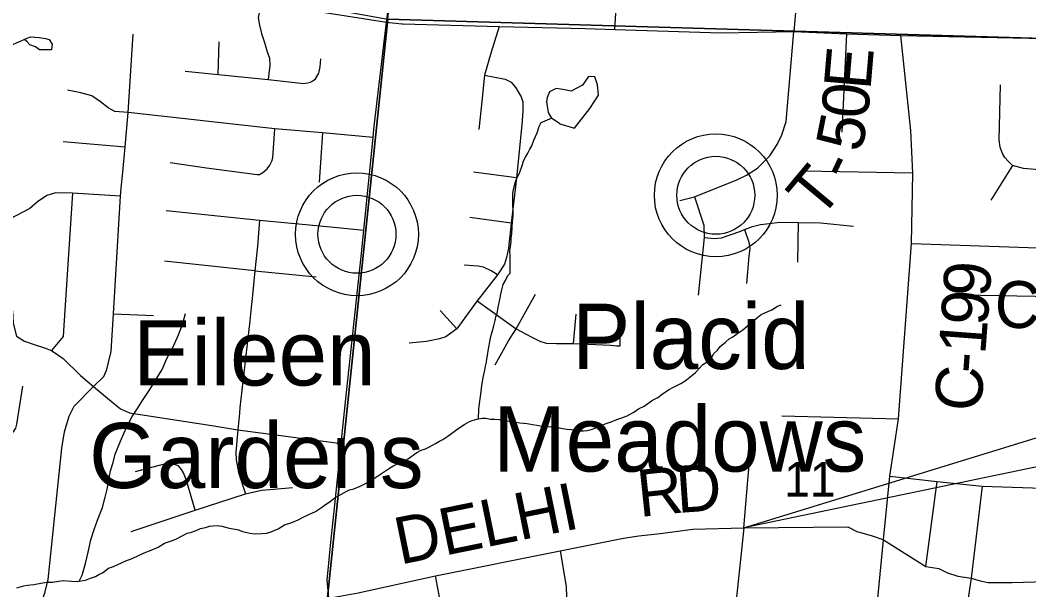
# Model space of a CAD drawing. Extents: x 0 to 34, y -2 to 22.
# Drawn here: x 4.698 to 5.919, y 16.041 to 16.731 of the extents above; entities that cross this region are included whole.
import ezdxf

# ---------------------------------------------------------------- set-up
doc = ezdxf.new("R2010")
doc.units = 0
for name, color, linetype in [('GM_X_County_Road', 7, 'Continuous'), ('GM_X_County_Road_Text', 7, 'Continuous'), ('GM_X_Minor_Lake', 7, 'Continuous'), ('GM_X_Minor_River', 7, 'Continuous'), ('GM_X_Section', 7, 'Continuous'), ('GM_X_Section_Text', 7, 'Continuous'), ('GM_X_Township_Road', 7, 'Continuous'), ('GM_X_Township_Road_Text', 7, 'Continuous'), ('GM_X_Unincorporated', 7, 'Continuous'), ('GM_X_Unincorporated_Location', 7, 'Continuous'), ('GM_X_Unincorporated_Text', 7, 'Continuous'), ('SH_Data', 7, 'Continuous'), ('SH_Text', 7, 'Continuous')]:
    doc.layers.add(name, color=color, linetype=linetype)

msp = doc.modelspace()

# ---------------------------------------------------------------- linework, layer by layer
at = {"layer": 'GM_X_County_Road'}
msp.add_line((5.6417, 16.798), (5.6344, 16.7168), dxfattribs=at)
for points in [[(5.075, 16.1095), (5.0801, 16.1592), (5.0864, 16.2182), (5.0917, 16.2685), (5.1105, 16.4445), (5.1137, 16.4765), (5.125, 16.5888), (5.1259, 16.5986), (5.1413, 16.7282), (5.1541, 16.8214), (5.1564, 16.873), (5.1627, 16.9374), (5.1803, 17.1286), (5.1858, 17.1668)], [(4.9892, 16.752), (5.1413, 16.7282), (5.1599, 16.7264), (5.1609, 16.7264)], [(5.1609, 16.7264), (5.2776, 16.7232), (5.3822, 16.7204), (5.4178, 16.7193), (5.5463, 16.7152), (5.6344, 16.7168)], [(5.6344, 16.7168), (5.6981, 16.7142), (5.7642, 16.7123)], [(5.7432, 16.1015), (5.7506, 16.1784), (5.7611, 16.248), (5.7771, 16.4603), (5.7787, 16.5454), (5.7761, 16.597), (5.7642, 16.7123)], [(5.7642, 16.7123), (5.9195, 16.7087), (5.9635, 16.7073), (5.991, 16.7068), (6.1316, 16.7045)], [(5.7771, 16.4603), (5.9772, 16.4534), (6.1008, 16.4492), (6.222, 16.4333), (6.2538, 16.4291)], [(5.7506, 16.1784), (5.8081, 16.1722), (5.8625, 16.1664), (5.9478, 16.1635), (6.0702, 16.1495), (6.1855, 16.1382), (6.345, 16.1172), (6.3726, 16.1142), (6.4077, 16.1125), (6.4437, 16.112), (6.4766, 16.1114), (6.5789, 16.1097)], [(5.0285, 16.0123), (5.0457, 16.0195), (5.0715, 16.0307), (5.1068, 16.0374), (5.2004, 16.0579), (5.3517, 16.0882), (5.4284, 16.1035), (5.4467, 16.1064), (5.4725, 16.1091), (5.512, 16.1143), (5.5739, 16.1159), (5.6997, 16.1172), (5.7116, 16.111), (5.7142, 16.1106), (5.7294, 16.1063), (5.734, 16.1047)], [(5.07, 16.0607), (5.0743, 16.1026), (5.075, 16.1095)], [(5.7054, 15.7447), (5.7226, 15.8889), (5.7432, 16.1015)], [(5.734, 16.1047), (5.7432, 16.1015), (5.7945, 16.0693), (5.8101, 16.0667), (5.8206, 16.0614), (5.8332, 16.0573), (5.8492, 16.0548), (5.8602, 16.0518), (5.8698, 16.0499), (5.8987, 16.0499), (5.9535, 16.0513)], [(5.0715, 16.0307), (5.0692, 16.0529), (5.07, 16.0607)], [(5.2096, 16.0107), (5.2004, 16.0579)]]:
    msp.add_lwpolyline(points, dxfattribs=at)
at = {"layer": 'GM_X_Minor_Lake'}
for points in [[(4.6858, 16.6999), (4.7062, 16.7089), (4.71, 16.7107), (4.7206, 16.7096), (4.7282, 16.7083), (4.7327, 16.7074), (4.7364, 16.7016), (4.7354, 16.6948), (4.732, 16.6949), (4.721, 16.6948), (4.7162, 16.6984), (4.7094, 16.7008), (4.7057, 16.7047)], [(4.7057, 16.7047), (4.7028, 16.7074)], [(5.3512, 16.6052), (5.3687, 16.6), (5.3874, 16.6238), (5.3981, 16.6399), (5.3969, 16.6525), (5.3933, 16.662), (5.3857, 16.6626), (5.3786, 16.6518), (5.3702, 16.6474), (5.3648, 16.6449), (5.3546, 16.6467), (5.3467, 16.648), (5.3386, 16.644), (5.3358, 16.6369)], [(5.3358, 16.637), (5.3349, 16.6319), (5.3369, 16.619), (5.3412, 16.612)], [(5.3512, 16.6052), (5.3412, 16.612)]]:
    msp.add_lwpolyline(points, dxfattribs=at)
at = {"layer": 'GM_X_Minor_River'}
for points in [[(5.2911, 16.4242), (5.2909, 16.4451), (5.2907, 16.4512), (5.2912, 16.4565), (5.2921, 16.4622), (5.2923, 16.4671), (5.2928, 16.4717), (5.2934, 16.4797), (5.2939, 16.4869), (5.2945, 16.4933), (5.2947, 16.4998), (5.2941, 16.5082), (5.294, 16.5158), (5.2941, 16.5211), (5.295, 16.5253), (5.2963, 16.5306), (5.2975, 16.5348), (5.2992, 16.5393), (5.3024, 16.5453), (5.3057, 16.5559), (5.307, 16.5604), (5.3097, 16.5649), (5.3125, 16.5698), (5.3149, 16.5743), (5.3173, 16.5784), (5.3198, 16.5852), (5.3235, 16.5942), (5.326, 16.6018), (5.3284, 16.6066), (5.3412, 16.6121)], [(5.2526, 16.2481), (5.2532, 16.2602), (5.2557, 16.2811), (5.2566, 16.2883), (5.2575, 16.2929), (5.2584, 16.2978), (5.2602, 16.3069), (5.2611, 16.3118), (5.2623, 16.3164), (5.2628, 16.3205), (5.2637, 16.3247), (5.2647, 16.3327), (5.2655, 16.3368), (5.2664, 16.3414), (5.2677, 16.3478), (5.2699, 16.3561), (5.2711, 16.3607), (5.2728, 16.3671), (5.2737, 16.3713), (5.2753, 16.3758), (5.2763, 16.3826), (5.2776, 16.3883), (5.2784, 16.3925), (5.2798, 16.3989), (5.281, 16.4042), (5.2824, 16.4106), (5.2852, 16.4155), (5.288, 16.4215), (5.2911, 16.4242)], [(5.3545, 16.2361), (5.3594, 16.2356), (5.3651, 16.235), (5.37, 16.2345), (5.3753, 16.2336), (5.3799, 16.2335), (5.384, 16.2337), (5.389, 16.2351), (5.3948, 16.2372), (5.399, 16.239), (5.4071, 16.2422), (5.4132, 16.2443), (5.4202, 16.2472), (5.4251, 16.2486), (5.4328, 16.2514), (5.4406, 16.2562), (5.4464, 16.2602), (5.4533, 16.2634), (5.4634, 16.2704), (5.4696, 16.2736), (5.475, 16.2777), (5.4827, 16.2832), (5.4889, 16.2864), (5.4978, 16.2907), (5.5028, 16.294), (5.511, 16.3003), (5.5153, 16.304), (5.5196, 16.3084), (5.5243, 16.3136), (5.5297, 16.3169), (5.5352, 16.3228), (5.5376, 16.327), (5.5422, 16.331), (5.5454, 16.3355), (5.5516, 16.3407), (5.5563, 16.3447), (5.5605, 16.3473), (5.5667, 16.3517), (5.5726, 16.3557), (5.5807, 16.3627), (5.5858, 16.3667), (5.5909, 16.3712), (5.5951, 16.3741), (5.6028, 16.3781), (5.6078, 16.3798), (5.6148, 16.3842), (5.6193, 16.386)], [(4.7688, 16.0513), (4.7725, 16.0586), (4.7766, 16.0726), (4.7799, 16.0865), (4.7833, 16.1013), (4.787, 16.1138), (4.791, 16.1254), (4.7971, 16.1405), (4.8004, 16.153), (4.8029, 16.1628), (4.8071, 16.1848), (4.81, 16.1949), (4.8125, 16.2052), (4.819, 16.221), (4.8261, 16.2368), (4.8333, 16.2507), (4.8396, 16.2604), (4.8455, 16.2702), (4.8545, 16.2833), (4.8631, 16.2972), (4.8694, 16.3077), (4.875, 16.3208), (4.8829, 16.3351), (4.8893, 16.3498), (4.8942, 16.3622), (4.8979, 16.3754)], [(4.6936, 16.0432), (4.702, 16.0456), (4.7066, 16.0466), (4.7139, 16.0475), (4.7227, 16.0488), (4.7299, 16.0501), (4.7368, 16.0503), (4.7498, 16.0523), (4.7596, 16.0512), (4.7665, 16.051), (4.7714, 16.0517), (4.7768, 16.0526), (4.7829, 16.0548), (4.7887, 16.0569), (4.7929, 16.0594), (4.7972, 16.0616), (4.8045, 16.0671), (4.8107, 16.0692), (4.8157, 16.0714), (4.8257, 16.076), (4.833, 16.0789), (4.8476, 16.0857), (4.8561, 16.0889), (4.8645, 16.0925), (4.8723, 16.0972), (4.8807, 16.1), (4.8861, 16.1021), (4.8938, 16.1061), (4.8996, 16.1094), (4.9038, 16.1104), (4.9107, 16.1129), (4.9161, 16.115), (4.9219, 16.1164), (4.9268, 16.1178), (4.9314, 16.1184), (4.936, 16.1187), (4.9417, 16.1181), (4.9507, 16.1156), (4.9602, 16.1138), (4.967, 16.1117), (4.9719, 16.1104), (4.9761, 16.1095), (4.9814, 16.1086), (4.9905, 16.1091), (4.9958, 16.1094), (5.0004, 16.1108), (5.01, 16.1147), (5.0178, 16.1194), (5.0266, 16.1222), (5.0343, 16.1258), (5.0393, 16.1283), (5.047, 16.1319), (5.0551, 16.1359), (5.0625, 16.1406), (5.0675, 16.1443), (5.0729, 16.148), (5.0791, 16.1527), (5.0865, 16.1567), (5.0923, 16.16), (5.0965, 16.1618), (5.1015, 16.1632), (5.1092, 16.1664), (5.1134, 16.1685), (5.1204, 16.1722), (5.1254, 16.1751), (5.1339, 16.1809), (5.1389, 16.1842), (5.1436, 16.1875), (5.1502, 16.1915), (5.1621, 16.1965), (5.1679, 16.1998), (5.178, 16.2071), (5.183, 16.21), (5.1884, 16.2118), (5.1926, 16.2136), (5.2007, 16.2179), (5.2053, 16.2208), (5.2096, 16.223), (5.2154, 16.227), (5.2263, 16.2351), (5.2305, 16.238), (5.2359, 16.2413), (5.2417, 16.2446), (5.2463, 16.2463), (5.2506, 16.2477), (5.2571, 16.2487), (5.2616, 16.2486), (5.2669, 16.2477), (5.2722, 16.2475), (5.2775, 16.247), (5.2821, 16.2461), (5.2923, 16.2447), (5.3025, 16.2429), (5.3116, 16.2422), (5.3181, 16.2409), (5.3234, 16.2404), (5.3294, 16.2391), (5.3336, 16.239), (5.3439, 16.2379), (5.3488, 16.2374), (5.3545, 16.2361)]]:
    msp.add_lwpolyline(points, dxfattribs=at)
at = {"layer": 'GM_X_Section'}
for points in [[(5.25, 17.7471), (6.241, 17.6971), (6.1288, 16.703), (5.1427, 16.732)], [(5.1427, 16.732), (5.0363, 15.7105), (4.012, 15.9002), (4.1192, 16.9159)], [(6.1288, 16.703), (6.0281, 15.6802), (5.0363, 15.7105), (5.1427, 16.732)]]:
    msp.add_lwpolyline(points, close=True, dxfattribs=at)
at = {"layer": 'GM_X_Township_Road'}
for p, q in [((5.6981, 16.7142), (5.6925, 16.5949)), ((4.9374, 16.6649), (4.9384, 16.7046)), ((5.0637, 16.5942), (5.0597, 16.5344)), ((4.7497, 16.5836), (4.8246, 16.5775)), ((5.8995, 16.5546), (5.8732, 16.5128)), ((5.2986, 16.5397), (5.2467, 16.5468)), ((5.7787, 16.5454), (5.6461, 16.5477)), ((5.292, 16.4847), (5.2422, 16.4919)), ((4.9874, 16.4883), (4.9849, 16.4572)), ((5.6397, 16.4855), (5.6391, 16.4378)), ((4.9818, 16.4272), (4.8722, 16.439)), ((4.9818, 16.4272), (5.0561, 16.4197)), ((5.2984, 16.3569), (5.3216, 16.3988)), ((4.8104, 16.3751), (4.8591, 16.3729)), ((5.2262, 16.357), (5.2062, 16.3793)), ((5.3677, 16.3391), (5.3707, 16.3747)), ((5.6198, 16.2514), (5.7611, 16.248)), ((5.5739, 16.1159), (5.5815, 16.2068)), ((5.7945, 16.0693), (5.8081, 16.1722)), ((5.8625, 16.1664), (5.8492, 16.0548))]:
    msp.add_line(p, q, dxfattribs=at)
for points in [[(5.4178, 16.7193), (5.4229, 16.8052), (5.4311, 16.9476)], [(4.9892, 16.752), (4.9856, 16.7334), (4.9874, 16.7247), (4.9899, 16.7145), (4.9936, 16.7038), (4.9966, 16.6923), (4.9995, 16.6846), (4.9997, 16.6757), (4.9986, 16.6658), (4.998, 16.6587)], [(5.2776, 16.7232), (5.268, 16.6921), (5.2597, 16.6642), (5.2591, 16.6565), (5.2571, 16.636), (5.253, 16.5982)], [(4.8199, 16.5274), (4.8217, 16.5465), (4.8246, 16.5775), (4.8285, 16.6188), (4.8342, 16.7138)], [(5.4963, 16.5124), (5.5142, 16.5169), (5.5656, 16.5374), (5.5773, 16.5428), (5.5906, 16.5513), (5.6053, 16.5666), (5.6145, 16.5803), (5.6198, 16.5919), (5.6253, 16.6078), (5.6344, 16.7168)], [(4.8974, 16.6688), (4.9374, 16.6649), (4.998, 16.6587), (5.0412, 16.6541), (5.0455, 16.6547), (5.0493, 16.6558), (5.0521, 16.6573), (5.055, 16.6595), (5.0592, 16.6665), (5.061, 16.6742), (5.0618, 16.6839)], [(5.2597, 16.6642), (5.285, 16.6593), (5.2921, 16.6556), (5.2977, 16.6487), (5.3006, 16.6441), (5.3041, 16.638), (5.3061, 16.6316), (5.3061, 16.6205), (5.3052, 16.6041), (5.2986, 16.5397), (5.292, 16.4847), (5.2889, 16.4546), (5.2864, 16.4433), (5.2839, 16.4353), (5.2755, 16.4222), (5.251, 16.3908), (5.2262, 16.357), (5.219, 16.3515), (5.2131, 16.3473), (5.2055, 16.3448), (5.1898, 16.3417), (5.1688, 16.3396)], [(6.0541, 16.535), (6.0012, 16.5411), (5.9459, 16.5482), (5.9128, 16.551), (5.8995, 16.5546), (5.894, 16.5601), (5.8901, 16.5645), (5.8872, 16.5693), (5.8844, 16.5768), (5.8833, 16.5859), (5.8846, 16.6524)], [(5.125, 16.5888), (5.0637, 16.5942), (5.006, 16.5992), (4.8285, 16.6188), (4.8123, 16.6202), (4.804, 16.6246), (4.7949, 16.6316), (4.7845, 16.6391), (4.7708, 16.6425), (4.7548, 16.6458)], [(4.8793, 16.5585), (4.9233, 16.552), (4.9846, 16.5436), (4.9875, 16.5439), (4.9914, 16.5461), (4.9965, 16.5505), (5, 16.5553), (5.0025, 16.56), (5.0036, 16.564), (5.006, 16.5992)], [(4.819, 16.5174), (4.7611, 16.5213), (4.7404, 16.5216), (4.7297, 16.5184), (4.7184, 16.5106), (4.7091, 16.5028), (4.6846, 16.4896)], [(4.7038, 16.0026), (4.7159, 16.0165), (4.7237, 16.0268), (4.728, 16.0386), (4.7315, 16.0532), (4.7333, 16.0727), (4.7481, 16.2124), (4.7513, 16.2323), (4.757, 16.2512), (4.763, 16.2633), (4.7862, 16.2871), (4.7989, 16.2992), (4.8026, 16.3075), (4.8047, 16.3161), (4.8077, 16.3293), (4.8104, 16.3751), (4.819, 16.5174), (4.8199, 16.5274)], [(4.7611, 16.5213), (4.7506, 16.3608), (4.7495, 16.3476), (4.7356, 16.3306)], [(5.5142, 16.5169), (5.5254, 16.4823), (5.5258, 16.4675), (5.5186, 16.3976)], [(4.8745, 16.5003), (4.9874, 16.4883), (5.0694, 16.481), (5.1137, 16.4765)], [(5.5258, 16.4675), (5.5387, 16.4662), (5.547, 16.4673), (5.5689, 16.4749), (5.5749, 16.4771), (5.5845, 16.481), (5.5942, 16.4833), (5.6047, 16.4846), (5.6175, 16.4859), (5.6397, 16.4855), (5.6667, 16.4851), (5.7069, 16.4811)], [(5.5749, 16.4771), (5.5799, 16.4617), (5.5812, 16.4541), (5.5798, 16.445), (5.577, 16.4117)], [(4.9849, 16.4572), (4.9818, 16.4272), (4.978, 16.3897), (4.9778, 16.3867)], [(5.2755, 16.4222), (5.2679, 16.4273), (5.2585, 16.4315), (5.2518, 16.4326), (5.2351, 16.4342)], [(5.9705, 16.3953), (5.861, 16.3972), (5.824, 16.3976)], [(4.9778, 16.3867), (4.9758, 16.3667), (4.9637, 16.2617), (4.9631, 16.2548)], [(5.251, 16.3908), (5.2984, 16.3569), (5.3163, 16.3474), (5.3268, 16.3419), (5.3345, 16.3396), (5.347, 16.3391), (5.3677, 16.3391), (5.4124, 16.3373), (5.4198, 16.3364), (5.4243, 16.3365), (5.4242, 16.3415), (5.4246, 16.3657), (5.4264, 16.3743)], [(4.6882, 16.3789), (4.689, 16.3637), (4.6932, 16.3481), (4.7029, 16.3419), (4.7157, 16.3377), (4.7271, 16.3341), (4.7356, 16.3306), (4.7495, 16.321), (4.7705, 16.3003), (4.7787, 16.2934)], [(5.2729, 16.3135), (5.2888, 16.3424), (5.2984, 16.3569)], [(4.6605, 16.2206), (4.6819, 16.2275), (4.6869, 16.2304), (4.6899, 16.2329), (4.6922, 16.2365), (4.6935, 16.2415), (4.7006, 16.2875)], [(4.7787, 16.2934), (4.7862, 16.2871), (4.8057, 16.2711), (4.8192, 16.2601), (4.8299, 16.2551), (4.9321, 16.2396), (4.9418, 16.238)], [(4.9631, 16.2548), (4.9613, 16.2348), (4.9588, 16.2076), (4.959, 16.1981), (4.962, 16.1828), (4.9706, 16.1571)], [(4.9418, 16.238), (4.9613, 16.2348), (5.0864, 16.2182)], [(4.9095, 16.1372), (4.8991, 16.1731), (4.8952, 16.1824), (4.8929, 16.1865), (4.8894, 16.1909), (4.8844, 16.1925), (4.8766, 16.1942), (4.866, 16.1915), (4.837, 16.1838)], [(4.832, 16.1114), (4.9095, 16.1372), (4.9706, 16.1571), (4.9896, 16.1617), (5.0048, 16.1629), (5.0275, 16.1648)], [(5.5739, 16.1159), (5.5645, 16.0279), (5.5645, 16.0222), (5.5648, 16.0201), (5.5655, 16.0184), (5.5662, 16.0171), (5.5672, 16.016), (5.5742, 16.0105)], [(5.3517, 16.0882), (5.3586, 16.0447), (5.3594, 16.02), (5.3546, 15.9807), (5.3498, 15.9651), (5.3479, 15.9601)], [(5.8492, 16.0548), (5.8398, 15.9932), (5.8283, 15.986), (5.8209, 15.9778), (5.8145, 15.9738), (5.8127, 15.9717), (5.8113, 15.9686), (5.8103, 15.9614), (5.8088, 15.9448), (5.801, 15.8802), (5.7878, 15.7705)]]:
    msp.add_lwpolyline(points, dxfattribs=at)
at = {"layer": 'GM_X_Unincorporated'}
for centre, radius in [((5.54, 16.5186), 0.0744), ((5.54, 16.5186), 0.0472), ((5.1054, 16.4714), 0.0744), ((5.1054, 16.4714), 0.0472)]:
    msp.add_circle(centre, radius, dxfattribs=at)
at = {"layer": 'GM_X_Unincorporated_Location'}
for p, q in [((5.54, 16.5186), (5.54, 16.5186)), ((5.1054, 16.4714), (5.1054, 16.4714))]:
    msp.add_line(p, q, dxfattribs=at)
at = {"layer": 'SH_Data'}
msp.add_lwpolyline([(5.5739, 16.1159), (9.9248, 17.4558), (9.9244, 17.0214)], close=True, dxfattribs=at)
at = {"layer": 'SH_Text'}
msp.add_lwpolyline([(5.5739, 16.1159), (5.5645, 16.0279), (5.5672, 16.016), (5.5742, 16.0105)], dxfattribs=at)

# ---------------------------------------------------------------- texts
at = {"layer": 'GM_X_County_Road_Text'}
for s, height, rotation, p in [('9', 0.0568, 86.1148, (5.8715, 16.3945)), ('C-210', 0.05682, 358.0725, (5.8769, 16.3589)), ('9', 0.0568, 85.8234, (5.8689, 16.3596)), ('1', 0.0568, 85.7243, (5.8663, 16.3249)), ('-', 0.0568, 85.6925, (5.8646, 16.3018)), ('C', 0.0568, 85.6901, (5.8611, 16.2556)), ('R', 0.0568, 6, (5.4478, 16.129)), ('D', 0.0568, 4.0176, (5.4937, 16.1339)), ('DELHI', 0.05682, 11.4874, (5.1576, 16.0712))]:
    msp.add_text(s, height=height, rotation=rotation, dxfattribs=at).set_placement(p)
at = {"layer": 'GM_X_Section_Text'}
msp.add_text('11', height=0.04186, rotation=0, dxfattribs=at).set_placement((5.6227, 16.1538))
at = {"layer": 'GM_X_Township_Road_Text'}
for s, rotation, p in [('E', 85.0858, (5.7272, 16.6452)), ('0', 84.6987, (5.724, 16.61)), ('5', 78.8571, (5.7163, 16.5694)), ('-', 64.6372, (5.7015, 16.5337)), ('T', 50.1426, (5.6658, 16.4879))]:
    msp.add_text(s, height=0.0568, rotation=rotation, dxfattribs=at).set_placement(p)
at = {"layer": 'GM_X_Unincorporated_Text'}
for s, p in [('Placid', (5.366, 16.3083)), ('Eileen', (4.8344, 16.2883)), ('Meadows', (5.2702, 16.1841)), ('Gardens', (4.781, 16.1641))]:
    msp.add_text(s, height=0.07898, rotation=0, dxfattribs=at).set_placement(p)

doc.saveas('drawing.dxf')
